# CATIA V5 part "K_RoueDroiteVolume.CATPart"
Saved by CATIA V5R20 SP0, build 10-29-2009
Part number: roue_droite_volume
Bounding box of the stored display mesh (mm): x -199.964 to 199.964, y -633.75 to -553.75, z -199.97 to 199.97
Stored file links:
  G:\Khaled_CFAO_2011\ST2M\ST2M_GR1\cdurantin\cdurantin\Khaled\CAD_ThinkMOTION\K_RoueDroiteVolume.CATPart
  C:\Documents and Settings\cdurantin\Bureau\cdurantin\caddy.CATProduct
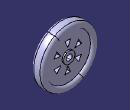
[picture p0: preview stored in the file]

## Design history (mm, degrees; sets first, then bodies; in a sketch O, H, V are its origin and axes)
Body1 (main body)
Body2
  Solid1: linked copy from another document
  Symmetry1: Reference zx-plane, ToTransfor Solid1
